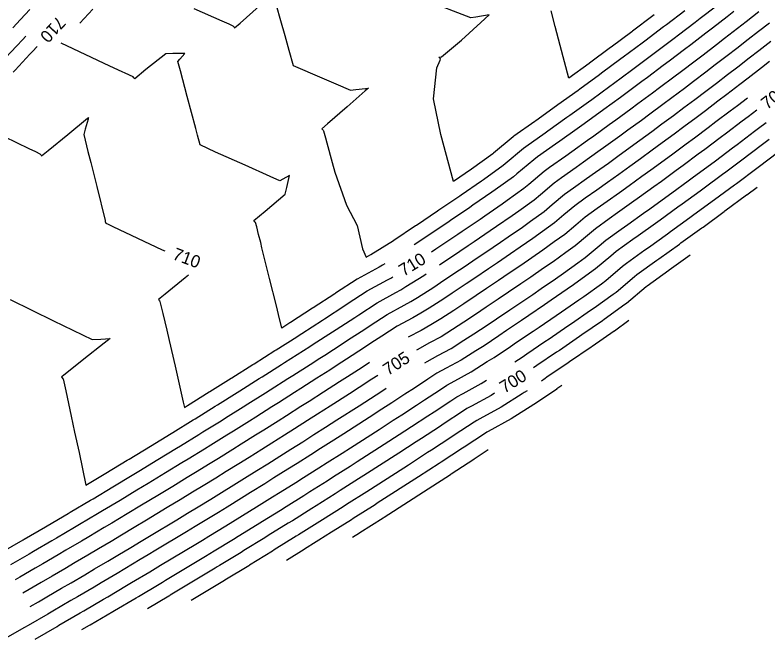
# Model space of a CAD drawing. Extents: x 1487507 to 1489130, y 497211 to 499439.
# Drawn here: x 1488338.2 to 1488484.6, y 498614.6 to 498736.1 of the extents above; entities that cross this region are included whole.
import ezdxf

# ---------------------------------------------------------------- set-up
doc = ezdxf.new("R2010")
doc.units = 0
for name, color, linetype in [('Prop CMT Ditch DDE', 7, 'Continuous'), ('Prop Drainage Ditch Flow Line', 7, 'Continuous'), ('Prop Drainage Structure Pipe Outlet Channel Detail CELL', 7, 'Continuous')]:
    doc.layers.add(name, color=color, linetype=linetype)

msp = doc.modelspace()

# ---------------------------------------------------------------- linework, layer by layer
at = {"layer": 'Prop CMT Ditch DDE'}
for points in [[(1488372.98, 498737.37), (1488378.39, 498734.96), (1488379.79, 498734.33), (1488380.57, 498733.99), (1488380.8, 498733.71), (1488380.9, 498733.61), (1488381.96, 498734.52), (1488385.7, 498737.77)], [(1488388.98, 498737.99), (1488389.84, 498734.98), (1488390.65, 498732.1), (1488391.45, 498729.26), (1488392.28, 498726.27), (1488397.84, 498723.85), (1488400.57, 498722.67), (1488403.43, 498721.44), (1488404.49, 498721.56), (1488406.34, 498721.77), (1488406.71, 498721.81), (1488406.92, 498721.84), (1488406.3, 498721.3), (1488402.76, 498718.21), (1488398.96, 498714.89), (1488397.87, 498713.94), (1488398.11, 498713.67), (1488398.2, 498713.57), (1488398.58, 498712.19), (1488398.83, 498711.25), (1488399.89, 498707.37), (1488400.39, 498705.49), (1488402.64, 498699.07), (1488404.7, 498695.13), (1488405.73, 498690.63), (1488406.47, 498689), (1488407.36, 498689.49), (1488407.38, 498689.5), (1488407.4, 498689.51), (1488411.78, 498692.25), (1488411.88, 498692.31), (1488416.08, 498695.12), (1488416.24, 498695.23), (1488420.37, 498698.01), (1488420.6, 498698.17), (1488424.65, 498700.92), (1488424.94, 498701.12), (1488428.92, 498703.84), (1488429.28, 498704.1), (1488433.11, 498706.86), (1488433.5, 498707.19), (1488437.04, 498710.18), (1488437.48, 498710.49), (1488441.27, 498713.17), (1488441.77, 498713.53), (1488445.48, 498716.18), (1488446.06, 498716.59), (1488449.69, 498719.21), (1488450.32, 498719.67), (1488453.87, 498722.26), (1488454.57, 498722.78), (1488458.04, 498725.34), (1488458.8, 498725.91), (1488462.19, 498728.44), (1488463.01, 498729.06), (1488466.33, 498731.56), (1488467.21, 498732.24), (1488470.45, 498734.71), (1488471.39, 498735.44), (1488474.55, 498737.88)], [(1488468.39, 498736.89), (1488464.83, 498734.18), (1488464.27, 498733.75), (1488460.65, 498731.01), (1488460.15, 498730.63), (1488456.44, 498727.87), (1488456, 498727.54), (1488452.22, 498724.75), (1488451.84, 498724.47), (1488447.98, 498721.65), (1488447.66, 498721.42), (1488443.72, 498718.58), (1488443.47, 498718.4), (1488439.44, 498715.53), (1488439.26, 498715.4), (1488435.17, 498712.5), (1488435.04, 498712.41), (1488431.22, 498709.18), (1488431.12, 498709.1), (1488426.98, 498706.13), (1488426.93, 498706.09), (1488423.47, 498703.72), (1488420.97, 498712.84), (1488419.55, 498719.76), (1488420.19, 498725.79), (1488420.83, 498727.3), (1488420.93, 498727.53), (1488420.62, 498727.87), (1488420.59, 498727.9), (1488421.14, 498727.93), (1488425.01, 498731.2), (1488428.76, 498734.59), (1488430.41, 498736.1), (1488427.78, 498735.67), (1488426.8, 498735.52), (1488418.04, 498738.91)], [(1488341.11, 498737.16), (1488339.27, 498735.19), (1488337.77, 498733.58)], [(1488350.82, 498734.51), (1488353.32, 498737.23)], [(1488477.94, 498736.75), (1488476.62, 498735.71), (1488473.77, 498733.51), (1488472.51, 498732.53), (1488469.59, 498730.3), (1488468.38, 498729.38), (1488465.38, 498727.11), (1488464.24, 498726.24), (1488461.16, 498723.95), (1488460.08, 498723.14), (1488456.92, 498720.81), (1488455.9, 498720.05), (1488452.66, 498717.69), (1488451.71, 498716.99), (1488448.39, 498714.6), (1488447.5, 498713.96), (1488444.1, 498711.53), (1488443.28, 498710.94), (1488439.8, 498708.48), (1488439.05, 498707.94), (1488435.79, 498705.19), (1488435.11, 498704.62), (1488431.57, 498702.07), (1488430.9, 498701.6), (1488427.23, 498699.08), (1488426.63, 498698.66), (1488422.88, 498696.12), (1488422.34, 498695.75), (1488418.52, 498693.17), (1488418.04, 498692.85), (1488415.83, 498691.38)], [(1488462.46, 498736.12), (1488462.22, 498735.93), (1488458.28, 498732.96), (1488458.1, 498732.82), (1488454.08, 498729.83), (1488453.96, 498729.74), (1488449.87, 498726.72), (1488449.81, 498726.67), (1488445.86, 498723.79), (1488444.2, 498730.17), (1488443.23, 498733.82), (1488442.46, 498736.87)], [(1488420.76, 498687.5), (1488421.97, 498688.32), (1488423.06, 498689.05), (1488426.28, 498691.23), (1488427.44, 498692.02), (1488430.59, 498694.15), (1488431.81, 498695), (1488434.88, 498697.1), (1488436.15, 498698.02), (1488439.1, 498700.13), (1488440.35, 498701.19), (1488443.05, 498703.47), (1488444.44, 498704.46), (1488447.3, 498706.49), (1488448.75, 498707.53), (1488451.54, 498709.51), (1488453.06, 498710.62), (1488455.76, 498712.56), (1488457.35, 498713.73), (1488459.97, 498715.64), (1488461.62, 498716.87), (1488464.16, 498718.74), (1488465.88, 498720.03), (1488468.33, 498721.86), (1488470.12, 498723.21), (1488472.49, 498725), (1488474.34, 498726.42), (1488476.63, 498728.17), (1488478.54, 498729.65), (1488480.76, 498731.36), (1488482.73, 498732.91), (1488484.86, 498734.58)], [(1488340.32, 498731.96), (1488339.68, 498731.26), (1488338.56, 498730.07), (1488336.31, 498727.68)], [(1488335.53, 498631.57), (1488339.78, 498634.03), (1488340, 498634.16), (1488344.14, 498636.58), (1488344.47, 498636.77), (1488348.51, 498639.15), (1488348.92, 498639.39), (1488352.88, 498641.74), (1488353.37, 498642.03), (1488357.25, 498644.35), (1488360.95, 498646.58), (1488362.25, 498647.37), (1488366, 498649.64), (1488369.6, 498651.84), (1488370.38, 498652.32), (1488373.93, 498654.51), (1488374.75, 498655.01), (1488378.26, 498657.19), (1488379.12, 498657.72), (1488382.59, 498659.9), (1488383.48, 498660.45), (1488386.92, 498662.62), (1488387.84, 498663.2), (1488391.25, 498665.37), (1488392.2, 498665.97), (1488395.58, 498668.13), (1488397.46, 498669.34), (1488398.41, 498669.95), (1488401.83, 498672.16), (1488402.84, 498672.82), (1488406.19, 498675), (1488407.26, 498675.71), (1488410.54, 498677.85), (1488413.89, 498679.67), (1488415.18, 498680.37), (1488416.45, 498681.17), (1488419.6, 498683.15), (1488420.93, 498684.04), (1488423.93, 498686.05), (1488425.33, 498686.99), (1488428.25, 498688.96), (1488429.72, 498689.97), (1488432.56, 498691.9), (1488434.1, 498692.96), (1488436.87, 498694.85), (1488438.44, 498695.99), (1488441.09, 498697.89), (1488442.64, 498699.2), (1488445.05, 498701.24), (1488446.75, 498702.45), (1488449.31, 498704.26), (1488451.08, 498705.53), (1488453.55, 498707.29), (1488455.4, 498708.63), (1488457.79, 498710.35), (1488459.7, 498711.75), (1488462, 498713.43), (1488463.98, 498714.9), (1488466.2, 498716.54), (1488468.24, 498718.07), (1488470.38, 498719.66), (1488472.48, 498721.26), (1488474.55, 498722.82), (1488476.71, 498724.48), (1488478.7, 498725.99), (1488480.92, 498727.72), (1488482.83, 498729.19), (1488485.12, 498730.99)], [(1488410.09, 498687.69), (1488409.66, 498687.43), (1488409.33, 498687.22), (1488408.99, 498687.03), (1488404.71, 498684.71), (1488400.54, 498681.98), (1488400.39, 498681.88), (1488396.14, 498679.12), (1488396.05, 498679.06), (1488391.73, 498676.28), (1488391.71, 498676.26), (1488391.66, 498676.23), (1488390.06, 498675.21), (1488389.43, 498677.86), (1488389.02, 498679.5), (1488387.71, 498684.85), (1488386.21, 498690.83), (1488385.97, 498691.81), (1488385.57, 498693.38), (1488385.19, 498694.88), (1488384.98, 498695.71), (1488384.84, 498695.87), (1488384.65, 498696.09), (1488386.86, 498697.94), (1488390.72, 498701.21), (1488391.02, 498702.55), (1488391.55, 498704.89), (1488390.25, 498704.15), (1488389.67, 498703.82), (1488387.8, 498704.66), (1488382.92, 498706.86), (1488377.18, 498709.43), (1488374.18, 498710.8), (1488373.68, 498712.72), (1488373.35, 498713.98), (1488371.68, 498720.26), (1488370.36, 498725.21), (1488369.88, 498727.03), (1488370.25, 498727.47), (1488371.21, 498728.62), (1488368.9, 498728.56), (1488367.55, 498728.52), (1488363.66, 498725.47), (1488361.51, 498723.67), (1488361.33, 498723.89), (1488361.19, 498724.05), (1488359.64, 498724.77), (1488359.03, 498725.05), (1488356.66, 498726.15), (1488347.21, 498730.58)], [(1488484.9, 498727.02), (1488483.31, 498725.79), (1488480.76, 498723.81), (1488479.09, 498722.54), (1488476.6, 498720.63), (1488474.85, 498719.31), (1488472.43, 498717.47), (1488470.6, 498716.11), (1488468.24, 498714.34), (1488466.33, 498712.93), (1488464.03, 498711.22), (1488462.04, 498709.77), (1488459.81, 498708.14), (1488457.73, 498706.64), (1488455.57, 498705.07), (1488453.41, 498703.53), (1488451.31, 498702.03), (1488449.07, 498700.44), (1488447.06, 498699), (1488444.92, 498697.2), (1488443.09, 498695.65), (1488440.74, 498693.96), (1488438.85, 498692.6), (1488436.39, 498690.91), (1488434.54, 498689.64), (1488432, 498687.91), (1488430.23, 498686.7), (1488427.6, 498684.93), (1488425.9, 498683.78), (1488423.19, 498681.97), (1488421.56, 498680.87), (1488418.71, 498679.09), (1488417.12, 498678.09), (1488415.52, 498677.21), (1488412.48, 498675.56), (1488409.51, 498673.62), (1488408.12, 498672.7), (1488405.07, 498670.72), (1488403.75, 498669.86), (1488400.63, 498667.85), (1488399.38, 498667.03), (1488396.88, 498665.43), (1488393.8, 498663.45), (1488392.52, 498662.65), (1488389.42, 498660.67), (1488388.16, 498659.88), (1488385.03, 498657.91), (1488383.78, 498657.13), (1488380.65, 498655.17), (1488379.41, 498654.4), (1488376.25, 498652.44), (1488375.03, 498651.68), (1488371.85, 498649.73), (1488370.64, 498648.99), (1488367.44, 498647.03), (1488364.11, 498645.01), (1488361.88, 498643.66), (1488358.63, 498641.7), (1488355.21, 498639.66), (1488354.21, 498639.07), (1488350.75, 498637.02), (1488349.8, 498636.45), (1488346.29, 498634.38), (1488345.38, 498633.85), (1488341.82, 498631.77), (1488340.94, 498631.26), (1488337.34, 498629.17)], [(1488480.59, 498719.93), (1488478.66, 498718.44), (1488477.22, 498717.36), (1488474.48, 498715.28), (1488472.96, 498714.14), (1488470.28, 498712.14), (1488468.68, 498710.96), (1488466.07, 498709.02), (1488464.38, 498707.79), (1488461.83, 498705.92), (1488460.07, 498704.65), (1488457.59, 498702.85), (1488455.73, 498701.53), (1488453.32, 498699.8), (1488451.39, 498698.43), (1488449.06, 498696.77), (1488447.2, 498695.2), (1488445.08, 498693.41), (1488443.03, 498691.94), (1488440.84, 498690.36), (1488438.67, 498688.87), (1488436.52, 498687.39), (1488434.28, 498685.86), (1488432.2, 498684.44), (1488429.87, 498682.87), (1488427.86, 498681.51), (1488425.46, 498679.9), (1488423.52, 498678.6), (1488420.97, 498677.01), (1488419.07, 498675.81), (1488417.16, 498674.76), (1488414.66, 498673.41)], [(1488417.9, 498668.44), (1488418.3, 498668.7), (1488420.42, 498669.85), (1488422.97, 498671.25), (1488425.49, 498672.84), (1488427.43, 498674.05), (1488429.98, 498675.76), (1488431.79, 498676.97), (1488434.41, 498678.75), (1488436.14, 498679.92), (1488438.84, 498681.76), (1488440.48, 498682.88), (1488443.25, 498684.79), (1488444.81, 498685.86), (1488447.61, 498687.88), (1488449.07, 498688.93), (1488451.77, 498691.21), (1488453.06, 498692.3), (1488456.02, 498694.41), (1488457.34, 498695.35), (1488460.39, 498697.53), (1488461.62, 498698.41), (1488464.74, 498700.67), (1488465.88, 498701.49), (1488469.07, 498703.83), (1488470.13, 498704.6), (1488473.38, 498707.01), (1488474.36, 498707.73), (1488477.68, 498710.22), (1488478.57, 498710.89), (1488481.96, 498713.46), (1488482.77, 498714.07), (1488484.23, 498715.2)], [(1488484.82, 498711.88), (1488484.32, 498711.51), (1488480.62, 498708.7), (1488480.04, 498708.26), (1488476.4, 498705.53), (1488475.73, 498705.04), (1488472.16, 498702.39), (1488471.41, 498701.85), (1488467.91, 498699.28), (1488467.08, 498698.68), (1488463.64, 498696.19), (1488462.71, 498695.53), (1488459.35, 498693.12), (1488458.34, 498692.4), (1488455.06, 498690.06), (1488454.05, 498689.21), (1488451.06, 498686.69), (1488449.9, 498685.85), (1488446.8, 498683.61), (1488445.54, 498682.75), (1488442.46, 498680.62), (1488441.12, 498679.71), (1488438.11, 498677.66), (1488436.68, 498676.69), (1488433.75, 498674.71), (1488432.24, 498673.7), (1488429.39, 498671.77), (1488427.76, 498670.75), (1488424.92, 498668.96), (1488422.05, 498667.39), (1488420.24, 498666.41), (1488418.47, 498665.25), (1488415.85, 498663.52), (1488414, 498662.32), (1488411.45, 498660.66), (1488409.53, 498659.41), (1488407.05, 498657.8), (1488402.11, 498654.63), (1488400.19, 498653.4), (1488397.6, 498651.76), (1488395.73, 498650.57), (1488393.08, 498648.9), (1488391.25, 498647.74), (1488388.55, 498646.06), (1488386.76, 498644.94), (1488383.99, 498643.22), (1488382.26, 498642.14), (1488379.42, 498640.4), (1488377.74, 498639.36), (1488374.82, 498637.58), (1488373.21, 498636.59), (1488371.52, 498635.57), (1488365.59, 498631.99), (1488364.11, 498631.1), (1488362.56, 498630.18), (1488359.55, 498628.38), (1488358.07, 498627.51), (1488354.97, 498625.67), (1488353.58, 498624.85), (1488350.34, 498622.95), (1488349.07, 498622.21), (1488345.58, 498620.18), (1488344.56, 498619.59), (1488340.75, 498617.39), (1488340.04, 498616.98), (1488335.81, 498614.56)], [(1488342.1, 498614.73), (1488346.37, 498617.19), (1488346.74, 498617.41), (1488350.89, 498619.82), (1488351.58, 498620.23), (1488355.4, 498622.47), (1488356.26, 498622.97), (1488359.9, 498625.13), (1488360.88, 498625.71), (1488364.4, 498627.81), (1488365.48, 498628.45), (1488366.52, 498629.07), (1488373.38, 498633.21), (1488374.65, 498633.98), (1488375.87, 498634.73), (1488379.21, 498636.77), (1488380.52, 498637.58), (1488383.76, 498639.57), (1488385.14, 498640.43), (1488388.29, 498642.38), (1488389.74, 498643.29), (1488392.8, 498645.2), (1488394.32, 498646.16), (1488397.3, 498648.04), (1488398.87, 498649.04), (1488401.79, 498650.89), (1488403.41, 498651.93), (1488408.97, 498655.5), (1488411.75, 498657.3), (1488413.38, 498658.35), (1488416.24, 498660.22), (1488417.78, 498661.23), (1488420.71, 498663.16), (1488422.18, 498664.12), (1488423.69, 498664.94), (1488426.87, 498666.68), (1488430.02, 498668.67), (1488431.34, 498669.5), (1488434.51, 498671.63), (1488435.72, 498672.44), (1488438.95, 498674.63), (1488440.08, 498675.4), (1488443.39, 498677.66), (1488444.44, 498678.37), (1488447.83, 498680.7), (1488448.79, 498681.36), (1488452.2, 498683.83), (1488453.06, 498684.45), (1488456.33, 498687.21), (1488457.07, 498687.83), (1488460.66, 498690.39), (1488461.36, 498690.89), (1488465.04, 498693.53), (1488465.66, 498693.97), (1488469.41, 498696.69), (1488469.93, 498697.07), (1488473.76, 498699.87), (1488474.19, 498700.19), (1488478.09, 498703.07), (1488478.44, 498703.33), (1488482.4, 498706.3), (1488482.66, 498706.5), (1488486.69, 498709.56)], [(1488435.38, 498668.62), (1488436.77, 498669.56), (1488437.68, 498670.17), (1488441.23, 498672.57), (1488442.06, 498673.13), (1488445.67, 498675.61), (1488446.42, 498676.12), (1488450.11, 498678.66), (1488450.77, 498679.11), (1488454.49, 498681.8), (1488455.05, 498682.2), (1488458.62, 498685.22), (1488459.07, 498685.59), (1488462.97, 498688.38), (1488463.37, 498688.67), (1488467.37, 498691.53), (1488467.67, 498691.75), (1488471.75, 498694.7), (1488471.96, 498694.85), (1488476.1, 498697.89), (1488476.23, 498697.98), (1488480.44, 498701.1), (1488480.48, 498701.13), (1488482.48, 498702.63)], [(1488337.24, 498680.75), (1488345.67, 498676.6), (1488353.18, 498672.95), (1488354.91, 498673.07), (1488356.68, 498673.19), (1488355.54, 498672.28), (1488351.58, 498669.13), (1488347.61, 498666), (1488347.24, 498665.71), (1488347.52, 498665.35), (1488347.55, 498665.31), (1488347.94, 498663.55), (1488348.06, 498662.97), (1488349.14, 498658.05), (1488349.8, 498654.97), (1488350.65, 498651.02), (1488351.97, 498644.67), (1488355.88, 498647), (1488360.03, 498649.5), (1488360.4, 498649.72), (1488364.56, 498652.25), (1488368.55, 498654.69), (1488368.9, 498654.91), (1488372.83, 498657.33), (1488373.25, 498657.58), (1488377.12, 498659.99), (1488377.59, 498660.28), (1488381.4, 498662.67), (1488381.93, 498662.99), (1488385.69, 498665.37), (1488386.26, 498665.73), (1488389.98, 498668.09), (1488390.6, 498668.48), (1488394.27, 498670.83), (1488395.54, 498671.65), (1488396.18, 498672.06), (1488399.9, 498674.46), (1488400.61, 498674.92), (1488404.25, 498677.29), (1488405.02, 498677.8), (1488408.6, 498680.14), (1488412.26, 498682.12), (1488413.23, 498682.65), (1488414.19, 498683.26), (1488417.65, 498685.42), (1488418.13, 498685.75)], [(1488457.55, 498676.65), (1488454.75, 498674.62), (1488454.69, 498674.58), (1488450.38, 498671.61), (1488450.23, 498671.51), (1488446, 498668.61), (1488445.77, 498668.45), (1488441.61, 498665.63), (1488441.29, 498665.42), (1488440.53, 498664.91)], [(1488407.12, 498668.5), (1488405.68, 498667.56), (1488402.85, 498665.74), (1488401.3, 498664.73), (1488398.19, 498662.73), (1488395.39, 498660.94), (1488393.79, 498659.92), (1488391, 498658.15), (1488389.39, 498657.13), (1488386.59, 498655.37), (1488384.97, 498654.36), (1488382.17, 498652.61), (1488380.55, 498651.6), (1488377.75, 498649.86), (1488376.13, 498648.86), (1488373.32, 498647.13), (1488371.69, 498646.14), (1488368.88, 498644.42), (1488365.96, 498642.65), (1488362.81, 498640.75), (1488360, 498639.05), (1488357.05, 498637.29), (1488355.55, 498636.4), (1488352.58, 498634.64), (1488351.1, 498633.76), (1488348.11, 498632), (1488346.62, 498631.13), (1488343.63, 498629.38), (1488342.1, 498628.49), (1488339.14, 498626.78), (1488338.23, 498626.25)], [(1488351.2, 498616.56), (1488352.7, 498617.43), (1488352.82, 498617.5), (1488357.22, 498620.08), (1488357.56, 498620.28), (1488361.73, 498622.75), (1488362.22, 498623.04), (1488366.24, 498625.43), (1488366.86, 498625.8), (1488367.44, 498626.16), (1488375.23, 498630.85), (1488376.09, 498631.38), (1488376.92, 498631.88), (1488380.68, 498634.18), (1488381.62, 498634.75), (1488385.26, 498637), (1488386.29, 498637.63), (1488389.81, 498639.82), (1488390.93, 498640.52), (1488394.35, 498642.66), (1488395.55, 498643.41), (1488398.88, 498645.51), (1488400.14, 498646.32), (1488403.39, 498648.38), (1488404.72, 498649.23), (1488410.88, 498653.19), (1488413.98, 498655.2), (1488415.3, 498656.05), (1488418.47, 498658.12), (1488419.72, 498658.94), (1488422.95, 498661.07), (1488424.12, 498661.83), (1488425.32, 498662.48), (1488428.81, 498664.4), (1488429.86, 498665.06)], [(1488341.18, 498621.08), (1488342.76, 498621.98), (1488344.42, 498622.95), (1488347.26, 498624.6), (1488349.1, 498625.68), (1488351.76, 498627.23), (1488353.68, 498628.37), (1488356.24, 498629.88), (1488358.22, 498631.05), (1488360.73, 498632.55), (1488362.74, 498633.75), (1488364.66, 498634.91), (1488369.67, 498637.93), (1488371.77, 498639.2), (1488373.78, 498640.43), (1488376.27, 498641.95), (1488378.32, 498643.22), (1488380.75, 498644.72), (1488382.85, 498646.02), (1488385.23, 498647.49), (1488387.36, 498648.82), (1488389.69, 498650.29), (1488391.85, 498651.65), (1488394.15, 498653.09), (1488396.33, 498654.48), (1488398.59, 498655.92), (1488400.8, 498657.33), (1488405.13, 498660.11), (1488407.3, 498661.52), (1488409.53, 498662.96), (1488410.37, 498663.51)], [(1488444.54, 498664.02), (1488443.57, 498663.37), (1488443.55, 498663.35), (1488439.17, 498660.4), (1488439.06, 498660.33), (1488434.66, 498657.56), (1488430.22, 498655.12), (1488429.94, 498654.97), (1488429.68, 498654.79), (1488425.52, 498652.05), (1488425.17, 498651.82), (1488421.08, 498649.15), (1488420.65, 498648.87), (1488416.64, 498646.26), (1488408.64, 498641.13), (1488408.19, 498640.84), (1488403.95, 498638.15), (1488403.61, 498637.93), (1488399.24, 498635.18), (1488399.01, 498635.04), (1488394.5, 498632.21), (1488394.4, 498632.15), (1488390.97, 498630.03)], [(1488437.74, 498663.03), (1488437.21, 498662.67), (1488436.8, 498662.42), (1488432.71, 498659.84), (1488428.59, 498657.57), (1488428, 498657.26), (1488427.44, 498656.89), (1488423.58, 498654.35), (1488422.93, 498653.92), (1488419.16, 498651.45), (1488418.42, 498650.98), (1488414.72, 498648.57), (1488407.33, 498643.83), (1488406.59, 498643.35), (1488402.68, 498640.87), (1488402.03, 498640.46), (1488398.01, 498637.92), (1488397.46, 498637.58), (1488393.31, 498634.98), (1488392.87, 498634.71), (1488388.58, 498632.05), (1488388.26, 498631.85), (1488383.81, 498629.11), (1488383.63, 498629), (1488379.01, 498626.18), (1488378.97, 498626.16), (1488378.94, 498626.14), (1488377.97, 498625.55), (1488372.42, 498622.2)], [(1488403.81, 498634.54), (1488405.19, 498635.41), (1488405.22, 498635.43), (1488409.79, 498638.33), (1488409.94, 498638.43), (1488418.55, 498643.96), (1488422.87, 498646.76), (1488423.01, 498646.85), (1488427.4, 498649.72), (1488427.45, 498649.76), (1488430.18, 498651.56)]]:
    msp.add_lwpolyline(points, dxfattribs=at)
at = {"layer": 'Prop Drainage Ditch Flow Line'}
for points in [[(1488419.2, 498690.05), (1488420.01, 498690.58), (1488420.79, 498691.11), (1488424.31, 498693.49), (1488425.16, 498694.07), (1488428.61, 498696.41), (1488429.52, 498697.04), (1488432.89, 498699.35), (1488433.86, 498700.05), (1488437.1, 498702.38), (1488438.07, 498703.19), (1488441.05, 498705.71), (1488442.12, 498706.47), (1488445.29, 498708.72), (1488446.43, 498709.53), (1488449.52, 498711.74), (1488450.73, 498712.61), (1488453.74, 498714.78), (1488455.01, 498715.71), (1488457.94, 498717.85), (1488459.27, 498718.84), (1488462.12, 498720.94), (1488463.52, 498721.99), (1488466.29, 498724.05), (1488467.75, 498725.16), (1488470.44, 498727.19), (1488471.96, 498728.36), (1488474.57, 498730.35), (1488476.16, 498731.58), (1488478.69, 498733.54), (1488480.33, 498734.83), (1488482.79, 498736.74)], [(1488342.51, 498729.94), (1488341.59, 498728.95), (1488341.1, 498728.43), (1488338.22, 498725.36), (1488337.86, 498724.98)], [(1488482.41, 498717.56), (1488480.71, 498716.26), (1488479.59, 498715.41), (1488476.52, 498713.08), (1488475.32, 498712.18), (1488472.32, 498709.93), (1488471.03, 498708.99), (1488468.1, 498706.81), (1488466.73, 498705.81), (1488463.86, 498703.71), (1488462.41, 498702.66), (1488459.6, 498700.63), (1488458.06, 498699.53), (1488455.33, 498697.58), (1488453.7, 498696.42), (1488451.06, 498694.53), (1488449.49, 498693.21), (1488447.08, 498691.17), (1488445.32, 498689.91), (1488442.83, 498688.11), (1488440.96, 498686.83), (1488438.5, 498685.13), (1488436.56, 498683.81), (1488434.17, 498682.18), (1488432.14, 498680.81), (1488429.83, 498679.24), (1488427.72, 498677.83), (1488425.47, 498676.32), (1488423.23, 498674.92), (1488421.02, 498673.53), (1488418.79, 498672.3), (1488416.36, 498670.99), (1488416.28, 498670.93)], [(1488336.07, 498712.47), (1488340.91, 498710.12), (1488342.17, 498709.52), (1488343.06, 498709.09), (1488343.27, 498708.83), (1488343.38, 498708.7), (1488344.64, 498709.73), (1488348.47, 498712.85), (1488352.28, 498715.99), (1488352.48, 498716.14), (1488352.45, 498716.04), (1488352.4, 498715.85), (1488351.87, 498713.91), (1488351.57, 498712.81), (1488352.39, 498709.56), (1488352.92, 498707.41), (1488354.09, 498702.75), (1488355.71, 498696.13), (1488355.76, 498695.93), (1488355.83, 498695.62), (1488356.3, 498695.4), (1488357.21, 498694.97), (1488366.83, 498690.44), (1488367.32, 498690.21)], [(1488469.48, 498689.38), (1488465.38, 498686.44), (1488465.29, 498686.37), (1488461.07, 498683.36), (1488460.9, 498683.22), (1488457.05, 498679.96), (1488456.78, 498679.77), (1488452.76, 498676.87), (1488452.4, 498676.62), (1488448.4, 498673.86), (1488447.95, 498673.56), (1488444.03, 498670.87), (1488443.5, 498670.51), (1488439.65, 498667.9), (1488439.03, 498667.49), (1488438.97, 498667.45)], [(1488371.91, 498685.51), (1488371.29, 498685), (1488367.37, 498681.8), (1488366.07, 498680.75), (1488366.28, 498680.49), (1488366.38, 498680.36), (1488366.69, 498679.07), (1488366.94, 498678.03), (1488367.7, 498674.79), (1488368.17, 498672.76), (1488369.33, 498667.79), (1488370.78, 498661.38), (1488370.92, 498660.77), (1488371.14, 498659.78), (1488371.73, 498660.15), (1488371.75, 498660.16), (1488375.97, 498662.78), (1488376.06, 498662.84), (1488380.21, 498665.43), (1488380.37, 498665.54), (1488384.46, 498668.11), (1488384.69, 498668.26), (1488388.71, 498670.81), (1488389, 498670.99), (1488392.97, 498673.53), (1488393.63, 498673.96), (1488393.96, 498674.17), (1488397.98, 498676.76), (1488398.37, 498677.02), (1488402.32, 498679.59), (1488402.78, 498679.89), (1488406.66, 498682.43), (1488410.62, 498684.58), (1488411.28, 498684.93), (1488411.64, 498685.16)], [(1488408.74, 498666), (1488407.6, 498665.26), (1488405.08, 498663.63), (1488403.21, 498662.42), (1488399.5, 498660.03), (1488396.99, 498658.43), (1488395.06, 498657.2), (1488392.57, 498655.62), (1488390.62, 498654.39), (1488388.14, 498652.83), (1488386.17, 498651.59), (1488383.7, 498650.05), (1488381.7, 498648.81), (1488379.25, 498647.29), (1488377.22, 498646.04), (1488374.79, 498644.54), (1488372.73, 498643.29), (1488370.33, 498641.81), (1488367.81, 498640.29), (1488363.74, 498637.83), (1488361.37, 498636.4), (1488358.89, 498634.92), (1488356.88, 498633.72), (1488354.41, 498632.26), (1488352.39, 498631.06), (1488349.93, 498629.62), (1488347.86, 498628.4), (1488345.44, 498626.99), (1488343.26, 498625.72), (1488340.95, 498624.38), (1488339.7, 498623.66)], [(1488431.42, 498662.54), (1488430.76, 498662.12), (1488426.95, 498660.03), (1488426.06, 498659.55), (1488425.19, 498658.98), (1488421.65, 498656.64), (1488420.7, 498656.02), (1488417.23, 498653.75), (1488416.2, 498653.09), (1488412.8, 498650.88), (1488406.03, 498646.53), (1488404.99, 498645.86), (1488401.41, 498643.59), (1488400.46, 498642.99), (1488396.78, 498640.67), (1488395.91, 498640.12), (1488392.12, 498637.75), (1488391.34, 498637.27), (1488387.43, 498634.84), (1488386.76, 498634.42), (1488382.71, 498631.93), (1488382.16, 498631.59), (1488377.96, 498629.03), (1488377.53, 498628.77), (1488377.09, 498628.49), (1488368.37, 498623.24), (1488368.23, 498623.15), (1488368.08, 498623.06), (1488363.96, 498620.61)]]:
    msp.add_lwpolyline(points, dxfattribs=at)

# ---------------------------------------------------------------- texts
at = {"layer": 'Prop Drainage Structure Pipe Outlet Channel Detail CELL'}
for s, rotation, p in [('710', 227.2285, (1488346.52, 498736.02)), ('705', 37.5468, (1488484.4, 498717.59)), ('710', 339.3954, (1488368.67, 498688.65)), ('710', 31.4687, (1488413.75, 498685.17)), ('705', 33.1208, (1488410.73, 498665.87)), ('700', 31.7012, (1488433.36, 498662.44))]:
    msp.add_text(s, height=2.4, rotation=rotation, dxfattribs=at).set_placement(p)

doc.saveas('drawing.dxf')
